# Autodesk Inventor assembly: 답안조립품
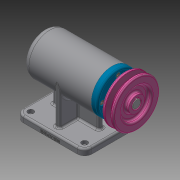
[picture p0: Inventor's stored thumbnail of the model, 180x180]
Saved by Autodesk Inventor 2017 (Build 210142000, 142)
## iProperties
Part Number: 답안조립품
Material: 일반
Document SubType Name: Assembly
Designer: 222
Author: 222
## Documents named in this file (12)
- C:\Users\222\Desktop\701004V1018\답안조립품.iam
- C:\Users\222\Desktop\701004V1018\본체.ipt
- C:\Users\222\Desktop\701004V1018\V벨트풀리.ipt
- C:\Users\222\Desktop\701004V1018\멈춤나사 M3.ipt
- C:\Users\222\Desktop\701004V1018\베어링 6004.ipt
- C:\Users\222\Desktop\701004V1018\베어링 51202.ipt
- C:\Users\222\Desktop\701004V1018\볼트 M4.ipt
- C:\Users\222\Desktop\701004V1018\어댑터슬리브.ipt
- C:\Users\222\Desktop\701004V1018\오일 실.ipt
- C:\Users\222\Desktop\701004V1018\축.ipt
- C:\Users\222\Desktop\701004V1018\커버.ipt
- C:\Users\222\Desktop\701004V1018\키 5 x 5 x 16.ipt
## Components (1 placed, 1 different names)
1. V벨트풀리:1 — 플러쉬:1
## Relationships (1: Flush 1)
- 플러쉬:1 [Flush]: V벨트풀리:1
